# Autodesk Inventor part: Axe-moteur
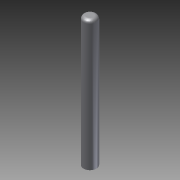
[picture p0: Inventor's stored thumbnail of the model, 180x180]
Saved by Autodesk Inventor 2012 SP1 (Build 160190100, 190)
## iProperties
Created: 2012-06
Part Number: Axe-moteur
Material: Default
Document SubType Name: Modeling
Designer: Bruno
Density: 1 g/cm^3
Author: Bruno
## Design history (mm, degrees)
sketch "Esquisse1"
  geometry: C1 r 1 at (0, 0); 1 further point
  constraints: 1 centre point, 1 coincident
  dimensions: "d0" = 2 diameter of C1
extrude "Extrusion1" new body sketch "Esquisse1" distance "d1" = 20; taper "d2" = 0 deg
fillet "Congé1" dims "d3" = 0.5
node "Solide1"
